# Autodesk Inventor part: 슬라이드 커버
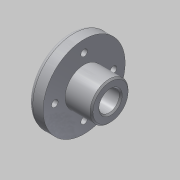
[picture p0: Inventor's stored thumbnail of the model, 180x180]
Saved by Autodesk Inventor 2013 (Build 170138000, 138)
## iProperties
Created: 2015-12
Part Number: 슬라이드 커버
Document SubType Name: Modeling
Designer: mdu
Density: 2.71 g/cm^3
Material: 알루미늄 6061
Mass: 76.471 g
Surface Area: 93.8237 cm^2
Volume: 28.2181 cm^3
Author: mdu
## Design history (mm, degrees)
sketch "스케치1"
  geometry: L1 (-14, 0)-(14, 0); L2 (-14, 0)-(-14, 28); L3 (-14, 28)-(-4, 28); L4 (-4, 28)-(-4, 13); L5 (-4, 13)-(14, 13); L6 (14, 13)-(14, 0); 2 further points
  constraints: 12 end point, 3 perpendicular, 1 coincident, 1 horizontal, 1 midpoint, 1 parallel
  dimensions: "d1" = 56 diameter of L3 L1; "d2" = 26 diameter of L5 L1; "d5" = 10 distance of L2.end L3.end; "d32" = 18 distance of L4.end L5.end
revolve "회전1" sketch "스케치1" stored, may be unused: angle "d6" = 90 deg
sketch "스케치2" dims "d33" = 40
  geometry: 3 further points
  constraints: 2 vertical alignment, 1 coincident, 2 other
hole "구멍1" sketch "스케치2" at (0, 20) diameter "d8" = 4.5; stored, may be unused: countersink angle "d12" = 90 deg, drill point angle "d14" = 118 deg; dims "d9" = 6, "d10" = 8, "d11" = 4.4, "d13" = 8
hole "구멍2" diameter "d20" = 14; stored, may be unused: countersink angle "d24" = 90 deg, drill point angle "d26" = 0 deg; dims "d18" = 10, "d19" = 10, "d21" = 6, "d22" = 8, "d23" = 4.4, "d25" = 8
fillet "모깎기1" dims "d27" = 3
chamfer "모따기1" distance "d29" = 1; stored, may be unused: second distance "d30" = 2, angle "d31" = 45 deg
node "솔리드1"
pattern_circular "원형 패턴1" dims angle "d16" = 360 deg
